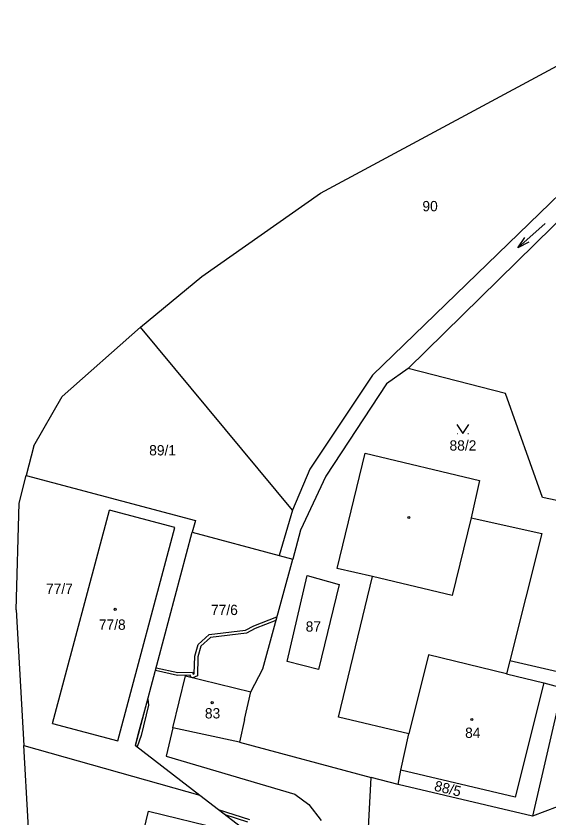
# Model space of a CAD drawing. Extents: x -670359 to -660124, y -978807 to -970072.
# Drawn here: x -670341.7 to -670253.9, y -977606.8 to -977474.6 of the extents above; entities that cross this region are included whole.
import ezdxf

# ---------------------------------------------------------------- set-up
doc = ezdxf.new("R2010")
doc.units = 0
for name, color, linetype in [('Hranice kat_území', 7, 'Continuous'), ('Hranice parcel', 7, 'Continuous'), ('Parcelní čísla', 7, 'Continuous'), ('Vnitřní kresba', 7, 'Continuous'), ('Věcná břemena k části', 7, 'Continuous'), ('Značky budov', 7, 'Continuous'), ('Značky kultur', 7, 'Continuous')]:
    doc.layers.add(name, color=color, linetype=linetype)

msp = doc.modelspace()

# ---------------------------------------------------------------- linework, layer by layer
at = {"layer": 'Hranice kat_území'}
for points in [[(-670291.52, -977503.81), (-670237.29, -977474.59)], [(-670311.06, -977517.51), (-670291.52, -977503.81)], [(-670321.21, -977525.91), (-670311.06, -977517.51)], [(-670334.09, -977537.34), (-670321.21, -977525.91)], [(-670338.79, -977545.47), (-670334.09, -977537.34)], [(-670338.79, -977545.47), (-670340.02, -977550.32)], [(-670341.18, -977554.89), (-670340.02, -977550.32)], [(-670341.71, -977572.48), (-670341.18, -977554.89)], [(-670341.71, -977572.48), (-670340.44, -977594.85)], [(-670336.85, -977658.05), (-670340.44, -977594.85)]]:
    msp.add_lwpolyline(points, dxfattribs=at)
at = {"layer": 'Hranice parcel'}
for points in [[(-670222.65, -977475.42), (-670282.93, -977533.78)], [(-670220.34, -977477.03), (-670277.08, -977532.7)], [(-670296.13, -977556.08), (-670321.21, -977525.91)], [(-670277.08, -977532.7), (-670280.62, -977535.23)], [(-670261.03, -977536.81), (-670277.08, -977532.7)], [(-670282.93, -977533.78), (-670293.29, -977549.3)], [(-670280.62, -977535.23), (-670290.65, -977550.44)], [(-670254.91, -977553.97), (-670261.03, -977536.81)], [(-670288.76, -977565.65), (-670284.14, -977546.65)], [(-670284.14, -977546.65), (-670265.29, -977551.18)], [(-670293.29, -977549.3), (-670296.13, -977556.08)], [(-670340.02, -977550.32), (-670312.13, -977557.76)], [(-670290.65, -977550.44), (-670294.8, -977559.37)], [(-670265.29, -977551.18), (-670266.7, -977557.33)], [(-670241.8, -977556.7), (-670254.91, -977553.97)], [(-670335.69, -977591.25), (-670326.3, -977556.05)], [(-670315.55, -977558.92), (-670326.3, -977556.05)], [(-670296.13, -977556.08), (-670298.32, -977563.52)], [(-670312.13, -977557.76), (-670312.65, -977559.69)], [(-670266.7, -977557.33), (-670255.03, -977559.89)], [(-670324.93, -977594.08), (-670315.55, -977558.92)], [(-670322.03, -977594.85), (-670312.65, -977559.69)], [(-670312.65, -977559.69), (-670298.32, -977563.52)], [(-670294.8, -977559.37), (-670296.1, -977564.11)], [(-670255.03, -977559.89), (-670260.3, -977580.88)], [(-670301.04, -977582.2), (-670296.1, -977564.11)], [(-670298.32, -977563.52), (-670296.1, -977564.11)], [(-670282.93, -977566.97), (-670288.76, -977565.65)], [(-670297.03, -977581.03), (-670293.73, -977566.81)], [(-670293.73, -977566.81), (-670288.46, -977568.29)], [(-670288.54, -977590.2), (-670282.93, -977566.97)], [(-670288.46, -977568.29), (-670291.84, -977582.34)], [(-670291.84, -977582.34), (-670297.03, -977581.03)], [(-670260.3, -977580.88), (-670260.88, -977583.04)], [(-670251.75, -977582.86), (-670260.3, -977580.88)], [(-670302.99, -977586.02), (-670301.04, -977582.2)], [(-670260.88, -977583.04), (-670254.73, -977584.52)], [(-670315.84, -977591.93), (-670313.78, -977583.39)], [(-670313.78, -977583.39), (-670302.99, -977586.02)], [(-670254.73, -977584.52), (-670259.42, -977603.36)], [(-670251.69, -977585.34), (-670256.57, -977606.5)], [(-670254.73, -977584.52), (-670251.69, -977585.34)], [(-670304.06, -977590.58), (-670302.99, -977586.02)], [(-670304.06, -977590.58), (-670304.89, -977594.33)], [(-670276.95, -977592.92), (-670288.54, -977590.2)], [(-670335.69, -977591.25), (-670324.93, -977594.08)], [(-670315.84, -977591.93), (-670316.97, -977596.6)], [(-670304.89, -977594.33), (-670315.84, -977591.93)], [(-670278.28, -977598.91), (-670276.95, -977592.92)], [(-670340.44, -977594.85), (-670311.4, -977603.07)], [(-670322.03, -977594.85), (-670311.4, -977603.07)], [(-670304.89, -977594.33), (-670283.19, -977600.11)], [(-670316.97, -977596.6), (-670295.77, -977602.9)], [(-670278.69, -977601.31), (-670278.28, -977598.91)], [(-670259.42, -977603.36), (-670278.28, -977598.91)], [(-670283.76, -977611.51), (-670283.19, -977600.11)], [(-670278.69, -977601.31), (-670283.19, -977600.11)], [(-670256.57, -977606.5), (-670278.69, -977601.31)], [(-670295.77, -977602.9), (-670293.42, -977604.61)], [(-670311.4, -977603.07), (-670304.57, -977608.35)], [(-670248.46, -977603.44), (-670256.57, -977606.5)], [(-670293.42, -977604.61), (-670291.41, -977607.22)], [(-670330.99, -977651.81), (-670319.86, -977605.66)], [(-670319.86, -977605.66), (-670307.72, -977608.63)]]:
    msp.add_lwpolyline(points, dxfattribs=at)
at = {"layer": 'Vnitřní kresba'}
for points in [[(-670266.7, -977557.33), (-670269.83, -977570.1)], [(-670269.83, -977570.1), (-670282.93, -977566.97)], [(-670273.74, -977579.91), (-670276.95, -977592.92)], [(-670260.88, -977583.04), (-670273.74, -977579.91)]]:
    msp.add_lwpolyline(points, dxfattribs=at)
at = {"layer": 'Věcná břemena k části'}
for p, q in [((-670302.51, -977575.12), (-670298.71, -977573.66)), ((-670303.87, -977575.83), (-670302.51, -977575.12)), ((-670298.87, -977574.26), (-670302.31, -977575.58)), ((-670311.66, -977578.2), (-670309.88, -977576.55)), ((-670309.88, -977576.55), (-670303.87, -977575.83)), ((-670303.71, -977576.31), (-670309.66, -977577.03)), ((-670302.31, -977575.58), (-670303.71, -977576.31)), ((-670309.66, -977577.03), (-670311.22, -977578.48)), ((-670312.26, -977580.15), (-670311.66, -977578.2)), ((-670311.22, -977578.48), (-670311.76, -977580.23)), ((-670312.32, -977583.03), (-670312.26, -977580.15)), ((-670311.76, -977580.23), (-670311.82, -977583.37)), ((-670315.09, -977583.31), (-670318.74, -977582.51)), ((-670318.61, -977582.03), (-670315.05, -977582.81)), ((-670315.05, -977582.81), (-670312.62, -977582.76)), ((-670312.62, -977582.76), (-670312.52, -977583.12)), ((-670312.52, -977583.12), (-670312.32, -977583.03)), ((-670313, -977583.26), (-670315.09, -977583.31)), ((-670312.91, -977583.6), (-670313, -977583.26)), ((-670312.58, -977583.68), (-670312.91, -977583.6)), ((-670311.82, -977583.37), (-670312.58, -977583.68)), ((-670319.89, -977588.21), (-670321.08, -977593.21)), ((-670319.99, -977587.21), (-670319.89, -977588.21)), ((-670321.08, -977593.21), (-670321.74, -977595.08)), ((-670308.39, -977605.4), (-670303.24, -977607.08)), ((-670303.48, -977607.52), (-670307.22, -977606.3))]:
    msp.add_line(p, q, dxfattribs=at)
for points in [[(-670298.71, -977573.66), (-670298.87, -977574.26)], [(-670318.74, -977582.51), (-670318.61, -977582.03)], [(-670321.74, -977595.08), (-670322.03, -977594.85), (-670321.56, -977593.07), (-670319.99, -977587.21)], [(-670307.22, -977606.3), (-670308.39, -977605.4)]]:
    msp.add_lwpolyline(points, dxfattribs=at)
at = {"layer": 'Značky budov'}
for centre in [(-670325.36, -977572.4), (-670309.37, -977587.8), (-670266.56, -977590.56)]:
    msp.add_circle(centre, 0.175, dxfattribs=at)
at = {"layer": 'Značky kultur'}
for p, q in [((-670254.5, -977508.82), (-670258.98, -977512.8)), ((-670269.01, -977543.43), (-670268.91, -977543.43)), ((-670267.21, -977543.43), (-670267.11, -977543.43))]:
    msp.add_line(p, q, dxfattribs=at)
for points in [[(-670257.16, -977511.85), (-670258.98, -977512.8), (-670257.82, -977511.1)], [(-670269.06, -977541.93), (-670268.06, -977543.43), (-670267.06, -977541.93)]]:
    msp.add_lwpolyline(points, dxfattribs=at)
for centre in [(-670276.97, -977557.28), (-670325.36, -977572.4), (-670309.37, -977587.8), (-670266.56, -977590.56)]:
    msp.add_circle(centre, 0.175, dxfattribs=at)

# ---------------------------------------------------------------- texts
at = {"layer": 'Parcelní čísla'}
for s, p in [('90', (-670274.72, -977506.78)), ('88/2', (-670270.25, -977546.24)), ('89/1', (-670319.76, -977547.03)), ('77/7', (-670336.77, -977569.87)), ('77/6', (-670309.57, -977573.35)), ('77/8', (-670328.06, -977575.78)), ('87', (-670293.96, -977576.09)), ('83', (-670310.58, -977590.4)), ('84', (-670267.68, -977593.61))]:
    msp.add_text(s, height=1.7, dxfattribs=at).set_placement(p)
msp.add_text('88/5', height=1.7, rotation=346.3321, dxfattribs=at).set_placement((-670272.88, -977602.27))

doc.saveas('drawing.dxf')
